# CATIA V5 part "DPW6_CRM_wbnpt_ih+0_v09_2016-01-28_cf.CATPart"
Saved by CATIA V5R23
Part number: DPW6_CRM_wbnpt_ih+0_v09_2016-01-28_cf
Bounding box of the stored display mesh (mm): x 2349.5 to 66711.883, y 0 to 29460.152, z -65.658 to 8715.761
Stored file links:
  C:\Users\mrg\work\AIAA_DPW\DPW6\DLR_meshes\all\baseline\DPW6_CRM_wbnpt_ih+0_v09_2016-01-28_cf.CATPart

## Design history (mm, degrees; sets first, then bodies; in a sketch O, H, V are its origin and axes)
MechanicalRefPlane1 "xy-plane"
MechanicalRefPlane2 "yz-plane"
MechanicalRefPlane3 "zx-plane"
Set1
  DatumSurface1 to DatumSurface3
Body1 (main body)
